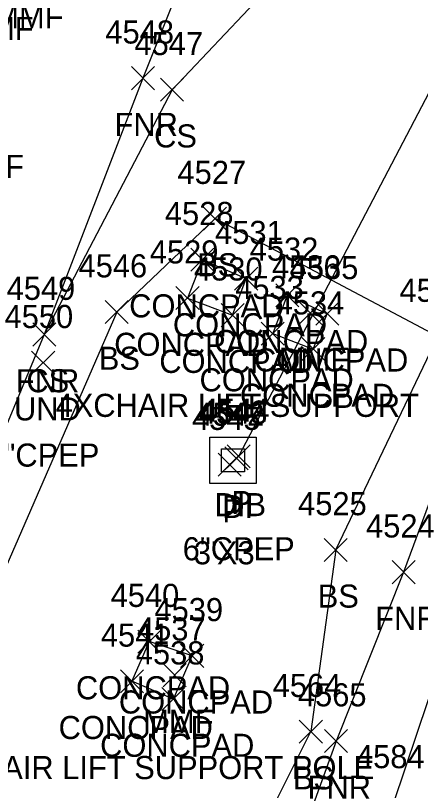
# Model space of a CAD drawing. Extents: x 49137 to 50946, y 9590 to 10709.
# Drawn here: x 50103 to 50138.1, y 10256.1 to 10323.2 of the extents above; entities that cross this region are included whole.
import ezdxf

# ---------------------------------------------------------------- set-up
doc = ezdxf.new("R2010")
doc.units = 0
for name, color, linetype in [('D_A', 7, 'Continuous'), ('D_C', 7, 'Continuous'), ('D_I', 7, 'Continuous'), ('D_TIC', 7, 'Continuous'), ('DCP', 7, 'Continuous'), ('DS', 7, 'Continuous'), ('L_A', 7, 'Continuous'), ('L_C', 7, 'Continuous'), ('L_I', 7, 'Continuous'), ('L_TIC', 7, 'Continuous'), ('LELB', 7, 'Continuous'), ('LFNC', 7, 'Continuous'), ('LS', 7, 'Continuous'), ('R_I', 7, 'Continuous'), ('RDP', 7, 'Continuous')]:
    doc.layers.add(name, color=color, linetype=linetype)

msp = doc.modelspace()

# ---------------------------------------------------------------- linework, layer by layer
at = {"layer": 'D_TIC'}
for points in [[(50104.402, 10292.179), (50106.402, 10294.179)], [(50106.402, 10292.179), (50104.402, 10294.179)], [(50121.167, 10283.888), (50123.167, 10285.888)], [(50123.167, 10283.888), (50121.167, 10285.888)], [(50121.343, 10284.066), (50123.343, 10286.066)], [(50123.343, 10284.066), (50121.343, 10286.066)], [(50120.564, 10283.355), (50122.564, 10285.355)], [(50122.564, 10283.355), (50120.564, 10285.355)]]:
    msp.add_lwpolyline(points, dxfattribs=at)
at = {"layer": 'DCP'}
msp.add_lwpolyline([(49941.688, 9827.483), (50059.335, 9808.365), (50181.403, 9733.094), (50281.739, 9743.292), (50422.723, 9892.522), (50122.338, 10663.607), (50179.929, 10552.611), (50179.639, 10394.452), (50122.343, 10285.066), (50121.564, 10284.355)], dxfattribs=at)
at = {"layer": 'DS'}
for p, q in [((50119.866, 10286.716), (50123.866, 10286.716)), ((50119.866, 10282.716), (50119.866, 10286.716)), ((50123.866, 10286.716), (50123.866, 10282.716)), ((50120.866, 10283.716), (50120.866, 10285.716)), ((50120.866, 10285.716), (50122.866, 10285.716)), ((50122.866, 10285.716), (50122.866, 10283.716)), ((50121.871, 10284.717), (50121.871, 10284.717)), ((50121.871, 10284.717), (50121.871, 10284.717)), ((50122.866, 10283.716), (50120.866, 10283.716)), ((50123.866, 10282.716), (50119.866, 10282.716))]:
    msp.add_line(p, q, dxfattribs=at)
at = {"layer": 'L_TIC'}
for points in [[(50113.055, 10316.815), (50115.055, 10318.815)], [(50115.055, 10316.815), (50113.055, 10318.815)], [(50115.581, 10315.815), (50117.581, 10317.815)], [(50117.581, 10315.815), (50115.581, 10317.815)], [(50119.307, 10304.659), (50121.307, 10306.659)], [(50121.307, 10304.659), (50119.307, 10306.659)], [(50118.215, 10301.1), (50120.215, 10303.1)], [(50120.215, 10301.1), (50118.215, 10303.1)], [(50118.215, 10301.1), (50120.215, 10303.1)], [(50120.215, 10301.1), (50118.215, 10303.1)], [(50122.003, 10299.463), (50124.003, 10301.463)], [(50124.003, 10299.463), (50122.003, 10301.463)], [(50122.003, 10299.463), (50124.003, 10301.463)], [(50124.003, 10299.463), (50122.003, 10301.463)], [(50116.916, 10297.771), (50118.916, 10299.771)], [(50118.916, 10297.771), (50116.916, 10299.771)], [(50125.571, 10298.016), (50127.571, 10300.016)], [(50127.571, 10298.016), (50125.571, 10300.016)], [(50125.571, 10298.016), (50127.571, 10300.016)], [(50127.571, 10298.016), (50125.571, 10300.016)], [(50110.788, 10296.567), (50112.788, 10298.567)], [(50112.788, 10296.567), (50110.788, 10298.567)], [(50120.826, 10296.294), (50122.826, 10298.294)], [(50122.826, 10296.294), (50120.826, 10298.294)], [(50127.56, 10296.485), (50129.56, 10298.485)], [(50129.56, 10296.485), (50127.56, 10298.485)], [(50129.041, 10296.414), (50131.041, 10298.414)], [(50131.041, 10296.414), (50129.041, 10298.414)], [(50129.041, 10296.414), (50131.041, 10298.414)], [(50131.041, 10296.414), (50129.041, 10298.414)], [(50104.504, 10294.618), (50106.504, 10296.618)], [(50106.504, 10294.618), (50104.504, 10296.618)], [(50104.504, 10294.618), (50106.504, 10296.618)], [(50106.504, 10294.618), (50104.504, 10296.618)], [(50124.313, 10294.7), (50126.313, 10296.7)], [(50126.313, 10294.7), (50124.313, 10296.7)], [(50127.819, 10293.357), (50129.819, 10295.357)], [(50129.819, 10293.357), (50127.819, 10295.357)], [(50129.767, 10275.969), (50131.767, 10277.969)], [(50131.767, 10275.969), (50129.767, 10277.969)], [(50129.767, 10275.969), (50131.767, 10277.969)], [(50131.767, 10275.969), (50129.767, 10277.969)], [(50135.657, 10274.04), (50137.657, 10276.04)], [(50137.657, 10274.04), (50135.657, 10276.04)], [(50113.6, 10268.029), (50115.6, 10270.029)], [(50115.6, 10268.029), (50113.6, 10270.029)], [(50117.322, 10266.797), (50119.322, 10268.797)], [(50119.322, 10266.797), (50117.322, 10268.797)], [(50115.798, 10265.119), (50117.798, 10267.119)], [(50117.798, 10265.119), (50115.798, 10267.119)], [(50112.099, 10264.587), (50114.099, 10266.587)], [(50114.099, 10264.587), (50112.099, 10266.587)], [(50112.099, 10264.587), (50114.099, 10266.587)], [(50114.099, 10264.587), (50112.099, 10266.587)], [(50115.697, 10263.049), (50117.697, 10265.049)], [(50117.697, 10263.049), (50115.697, 10265.049)], [(50115.697, 10263.049), (50117.697, 10265.049)], [(50117.697, 10263.049), (50115.697, 10265.049)], [(50127.611, 10260.23), (50129.611, 10262.23)], [(50129.611, 10260.23), (50127.611, 10262.23)], [(50127.611, 10260.23), (50129.611, 10262.23)], [(50129.611, 10260.23), (50127.611, 10262.23)], [(50129.797, 10259.419), (50131.797, 10261.419)], [(50131.797, 10259.419), (50129.797, 10261.419)]]:
    msp.add_lwpolyline(points, dxfattribs=at)
at = {"layer": 'LELB'}
for points in [[(50139.577, 10341.078), (50116.581, 10316.815), (50105.504, 10295.618)], [(50130.767, 10276.969), (50139.611, 10295.447), (50120.307, 10305.659), (50111.788, 10297.567), (50099.22, 10268.783), (50096.624, 10253.848), (50101.814, 10247.946), (50120.352, 10244.727), (50128.611, 10261.23)], [(50130.767, 10276.969), (50128.611, 10261.23)]]:
    msp.add_lwpolyline(points, dxfattribs=at)
at = {"layer": 'LFNC'}
for points in [[(50137.912, 10377.263), (50126.111, 10347.947), (50114.055, 10317.815), (50105.504, 10295.618), (50093.252, 10266.236)], [(50172.869, 10364.418), (50157.552, 10327.058), (50148.29, 10305.426), (50142.462, 10290.723), (50136.657, 10275.04), (50130.797, 10260.419), (50125.3, 10245.177), (50122.78, 10239.769), (50125.058, 10237.744)]]:
    msp.add_lwpolyline(points, dxfattribs=at)
at = {"layer": 'LS'}
for points in [[(50119.215, 10302.1), (50117.916, 10298.771), (50121.826, 10297.294), (50123.003, 10300.463)], [(50119.215, 10302.1), (50123.003, 10300.463)], [(50126.571, 10299.016), (50125.313, 10295.7), (50128.819, 10294.357), (50130.041, 10297.414)], [(50126.571, 10299.016), (50130.041, 10297.414)], [(50116.697, 10264.049), (50118.322, 10267.797), (50114.6, 10269.029), (50113.099, 10265.587)], [(50116.697, 10264.049), (50113.099, 10265.587)]]:
    msp.add_lwpolyline(points, dxfattribs=at)
at = {"layer": 'RDP'}
msp.add_lwpolyline([(50268.763, 10334.964), (50257.862, 10332.021), (50248.539, 10331.099), (50231.456, 10336.06), (50208.078, 10342.301), (50200.194, 10343.46), (50196.623, 10336.903), (50193.275, 10331.325), (50186.954, 10327.655), (50182.712, 10326.192), (50176.479, 10328.282), (50171.213, 10329.686), (50166.18, 10329.046), (50163.825, 10327.815), (50161.281, 10324.491), (50147.709, 10290.491), (50135.785, 10255.064), (50128.95, 10234.24), (50121.426, 10210.517), (50116.368, 10201.092), (50105.589, 10180.051)], dxfattribs=at)

# ---------------------------------------------------------------- texts
at = {"layer": 'D_A'}
for s, p in [('UND', (50102.875, 10288.179)), ('DIB', (50120.27, 10279.888)), ('DI', (50120.926, 10279.717)), ('P', (50121.721, 10280.066)), ('P', (50120.942, 10279.355))]:
    msp.add_text(s, height=2, dxfattribs=at).set_placement(p)
at = {"layer": 'D_C'}
for s, p in [('6"CPEP', (50100.56, 10284.179)), ('6"CPEP', (50117.5, 10276.066)), ("3'X3'", (50118.47, 10275.717))]:
    msp.add_text(s, height=2, dxfattribs=at).set_placement(p)
at = {"layer": 'D_I'}
for s, p in [('4550', (50102.056, 10296.179)), ('4542', (50118.611, 10287.717)), ('4543', (50118.907, 10287.888)), ('4544', (50119.083, 10288.066)), ('4545', (50118.304, 10287.355))]:
    msp.add_text(s, height=2, dxfattribs=at).set_placement(p)
at = {"layer": 'L_A'}
for s, p in [('MMF', (50101.079, 10322.142)), ('MMF', (50098.481, 10321.121)), ('FNR', (50111.591, 10312.815)), ('CS', (50115.022, 10311.815)), ('MMF', (50097.656, 10309.174)), ('BS', (50118.748, 10300.659)), ('CONCPAD', (50112.861, 10297.1)), ('CONCPAD', (50112.861, 10297.1)), ('CONCPAD', (50116.648, 10295.463)), ('CONCPAD', (50116.648, 10295.463)), ('CONCPAD', (50111.562, 10293.771)), ('CONCPAD', (50120.217, 10294.016)), ('CONCPAD', (50120.217, 10294.016)), ('BS', (50110.229, 10292.567)), ('CONCPAD', (50115.471, 10292.294)), ('CONCPAD', (50123.687, 10292.414)), ('CONCPAD', (50123.687, 10292.414)), ('MMF', (50125.844, 10292.485)), ('FNR', (50103.04, 10290.618)), ('CS', (50103.945, 10290.618)), ('CONCPAD', (50118.959, 10290.7)), ('CONCPAD', (50122.465, 10289.357)), ('BS', (50129.208, 10271.969)), ('BS', (50129.208, 10271.969)), ('FNR', (50134.192, 10270.04)), ('CONCPAD', (50108.245, 10264.029)), ('CONCPAD', (50111.968, 10262.797)), ('MMF', (50114.082, 10261.119)), ('CONCPAD', (50106.745, 10260.587)), ('CONCPAD', (50106.745, 10260.587)), ('CONCPAD', (50110.342, 10259.049)), ('CONCPAD', (50110.342, 10259.049)), ('BS', (50127.052, 10256.23)), ('BS', (50127.052, 10256.23)), ('FNR', (50128.332, 10255.419))]:
    msp.add_text(s, height=2, dxfattribs=at).set_placement(p)
at = {"layer": 'L_C'}
for p in [(50106.482, 10288.485), (50094.72, 10257.119)]:
    msp.add_text('4XCHAIR LIFT SUPPORT POLE', height=2, dxfattribs=at).set_placement(p)
at = {"layer": 'L_I'}
for s, p in [('4548', (50110.796, 10320.815)), ('4547', (50113.321, 10319.815)), ('4527', (50117.047, 10308.659)), ('4528', (50115.956, 10305.1)), ('4528', (50115.956, 10305.1)), ('4531', (50120.31, 10303.463)), ('4531', (50120.31, 10303.463)), ('4529', (50114.649, 10301.771)), ('4532', (50123.312, 10302.016)), ('4532', (50123.312, 10302.016)), ('4546', (50108.473, 10300.567)), ('4530', (50118.479, 10300.294)), ('4536', (50125.246, 10300.485)), ('4535', (50126.782, 10300.414)), ('4535', (50126.782, 10300.414)), ('4549', (50102.237, 10298.618)), ('4549', (50102.237, 10298.618)), ('4533', (50122.054, 10298.7)), ('4526', (50136.296, 10298.447)), ('4534', (50125.559, 10297.357)), ('4525', (50127.507, 10279.969)), ('4525', (50127.507, 10279.969)), ('4524', (50133.397, 10278.04)), ('4540', (50111.253, 10272.029)), ('4539', (50115.055, 10270.797)), ('4537', (50113.539, 10269.119)), ('4541', (50110.406, 10268.587)), ('4541', (50110.406, 10268.587)), ('4538', (50113.437, 10267.049)), ('4538', (50113.437, 10267.049)), ('4564', (50125.304, 10264.23)), ('4564', (50125.304, 10264.23)), ('4565', (50127.49, 10263.419))]:
    msp.add_text(s, height=2, dxfattribs=at).set_placement(p)
at = {"layer": 'R_I'}
msp.add_text('4584', height=2, dxfattribs=at).set_placement((50132.525, 10258.064))

doc.saveas('drawing.dxf')
